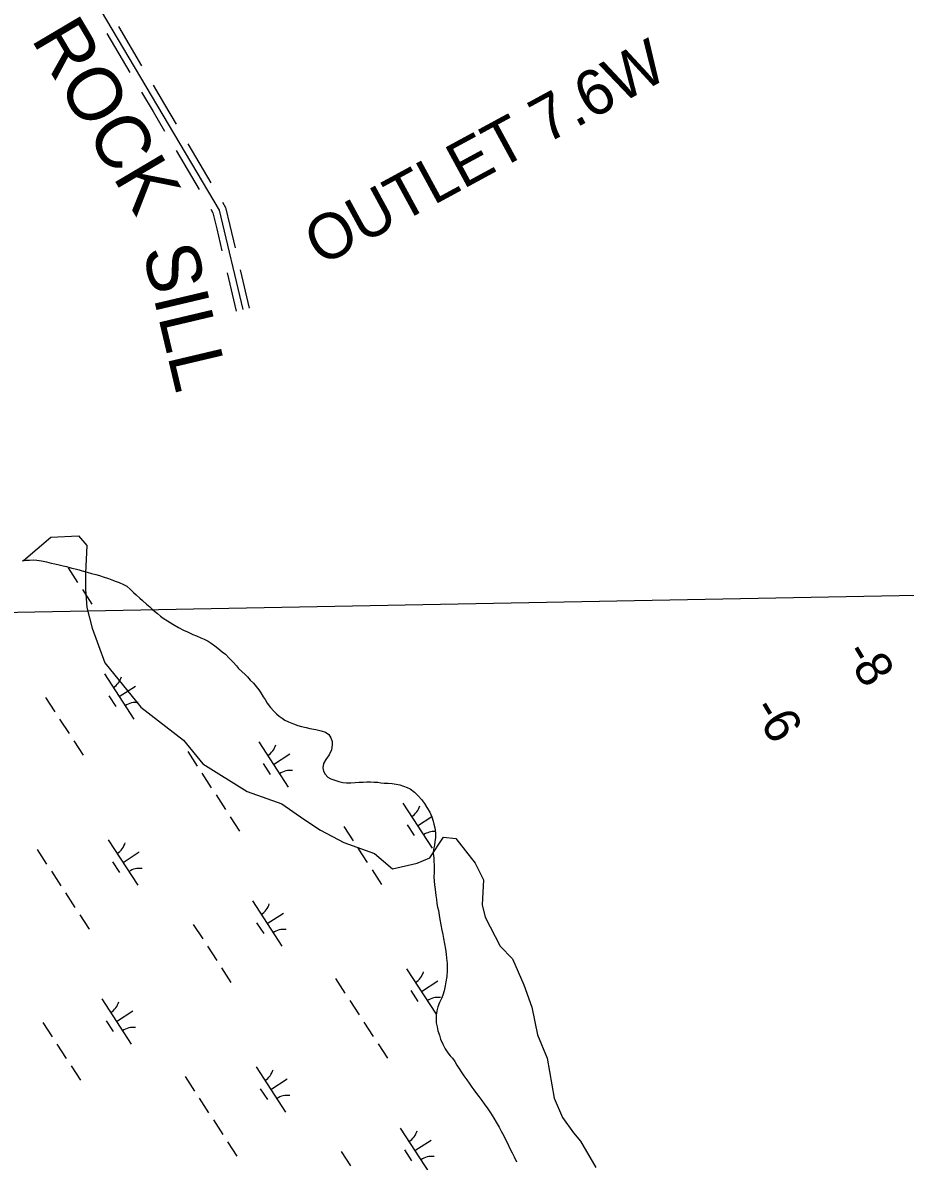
# Model space of a CAD drawing. Extents: x 3953924 to 3974542, y 193747 to 216192.
# Drawn here: x 3961535 to 3962352, y 205842 to 206897 of the extents above; entities that cross this region are included whole.
import ezdxf

# ---------------------------------------------------------------- set-up
doc = ezdxf.new("R2010")
doc.units = 0
for name, color, linetype in [('V-GRID-MAJR', 7, 'Continuous'), ('V-RIVR-EDGE', 7, 'Continuous'), ('V-RIVR-RANG', 7, 'Continuous'), ('V-RRAP-DIKE', 7, 'Continuous'), ('V-RRAP-SILL-IDEN', 7, 'Continuous'), ('V-WETL-SWMP', 7, 'Continuous')]:
    doc.layers.add(name, color=color, linetype=linetype)

msp = doc.modelspace()

# ---------------------------------------------------------------- linework, layer by layer
at = {"layer": 'V-GRID-MAJR'}
msp.add_spline([(3959356.8, 206310.4), (3962493.7, 206368.6), (3967818.6, 206468.2), (3970066, 206510.4)], degree=3, dxfattribs=at)
at = {"layer": 'V-RIVR-EDGE'}
msp.add_lwpolyline([(3961535.6, 206398.3), (3961560.9, 206420.1), (3961586.5, 206421.4), (3961594.2, 206412.4), (3961592.9, 206386.8), (3961592.9, 206371.5), (3961594.2, 206354.8), (3961599.3, 206335.6), (3961610.8, 206303.6), (3961644.1, 206262.6), (3961683.8, 206231.9), (3961701.8, 206210.1), (3961742.7, 206184.5), (3961774.7, 206173), (3961795.2, 206158.9), (3961810.6, 206148.6), (3961832.4, 206137.1), (3961860.6, 206126.9), (3961877.2, 206112.8), (3961900.3, 206117.9), (3961911.8, 206123), (3961924.6, 206142.2), (3961936.1, 206140.9), (3961954, 206117.9), (3961961.7, 206102.5), (3961960.4, 206079.5), (3961963, 206068), (3961977.1, 206041.1), (3961988.6, 206029.5), (3961998.9, 206005.2), (3962006.5, 205984.7), (3962011.7, 205959.1), (3962020.6, 205937.3), (3962027, 205900.2), (3962034.7, 205882.3), (3962045, 205868.2), (3962051.4, 205860.5), (3962065.5, 205836.2)], dxfattribs=at)
at = {"layer": 'V-RRAP-DIKE'}
for points in [[(3961596.7, 206925.9), (3961716.9, 206722.9), (3961738.7, 206630.9)], [(3961612.7, 206886.6), (3961634.1, 206850.4)], [(3961623.5, 206893), (3961644.9, 206856.8)], [(3961644.8, 206832.4), (3961655.5, 206814.3)], [(3961655.6, 206838.7), (3961666.3, 206820.7)], [(3961655.5, 206814.3), (3961666.2, 206796.2)], [(3961666.3, 206820.7), (3961677, 206802.6)], [(3961687.7, 206784.5), (3961709.1, 206748.4)], [(3961676.9, 206778.2), (3961698.3, 206742)], [(3961719.8, 206730.3), (3961722.7, 206725.3), (3961726.7, 206708.7)], [(3961709, 206723.9), (3961711, 206720.6), (3961714.5, 206705.8)], [(3961714.5, 206705.8), (3961719.3, 206685.4)], [(3961726.7, 206708.7), (3961731.5, 206688.2)], [(3961724.2, 206664.9), (3961732.6, 206629.4)], [(3961736.3, 206667.8), (3961744.7, 206632.3)]]:
    msp.add_lwpolyline(points, dxfattribs=at)
at = {"layer": 'V-WETL-SWMP'}
for p, q in [((3961534.2, 206398.1), (3961537.9, 206398.6)), ((3961537.9, 206398.6), (3961541.2, 206398.8)), ((3961541.2, 206398.8), (3961544.4, 206399.1)), ((3961544.4, 206399.1), (3961547.9, 206398.8)), ((3961547.9, 206398.8), (3961552.2, 206398.1)), ((3961552.2, 206398.1), (3961556.8, 206397.2)), ((3961556.8, 206397.2), (3961561.2, 206396)), ((3961561.2, 206396), (3961564.6, 206395.2)), ((3961564.6, 206395.2), (3961568.6, 206394.5)), ((3961568.6, 206394.5), (3961572.3, 206393.5)), ((3961572.3, 206393.5), (3961575.3, 206392.8)), ((3961575.3, 206392.8), (3961580.4, 206391.3)), ((3961577, 206391.5), (3961585.7, 206378.1)), ((3961580.4, 206391.3), (3961583.5, 206390.7)), ((3961583.5, 206390.7), (3961587, 206389.8)), ((3961587, 206389.8), (3961590, 206388.7)), ((3961590, 206388.7), (3961594.6, 206387.7)), ((3961594.6, 206387.7), (3961598.5, 206386.5)), ((3961598.5, 206386.5), (3961602.5, 206385.5)), ((3961602.5, 206385.5), (3961605.9, 206384.6)), ((3961605.9, 206384.6), (3961609.3, 206383.3)), ((3961609.3, 206383.3), (3961614.2, 206381.7)), ((3961614.2, 206381.7), (3961617.5, 206380.5)), ((3961617.5, 206380.5), (3961621.3, 206379.1)), ((3961621.3, 206379.1), (3961624.2, 206378.1)), ((3961590.1, 206371.4), (3961598.8, 206357.9)), ((3961624.2, 206378.1), (3961628.3, 206376.3)), ((3961628.3, 206376.3), (3961631.4, 206374.5)), ((3961631.4, 206374.5), (3961634.7, 206371.5)), ((3961634.7, 206371.5), (3961637.5, 206368.8)), ((3961637.5, 206368.8), (3961639.8, 206366.7)), ((3961639.8, 206366.7), (3961643.3, 206363.5)), ((3961643.3, 206363.5), (3961645.8, 206361.5)), ((3961645.8, 206361.5), (3961649.6, 206358)), ((3961649.6, 206358), (3961652.5, 206355.4)), ((3961652.5, 206355.4), (3961655.4, 206352.8)), ((3961655.4, 206352.8), (3961659.6, 206349.4)), ((3961659.6, 206349.4), (3961662.3, 206346.9)), ((3961662.3, 206346.9), (3961665, 206345)), ((3961665, 206345), (3961668.8, 206342.4)), ((3961668.8, 206342.4), (3961673.9, 206339.3)), ((3961673.9, 206339.3), (3961679.1, 206336.4)), ((3961679.1, 206336.4), (3961683.7, 206334)), ((3961683.7, 206334), (3961687.4, 206332.4)), ((3961687.4, 206332.4), (3961692.5, 206330)), ((3961692.5, 206330), (3961695.7, 206328.7)), ((3961695.7, 206328.7), (3961699.9, 206326.9)), ((3961699.9, 206326.9), (3961702.9, 206325.4)), ((3961702.9, 206325.4), (3961706.6, 206323.6)), ((3961706.6, 206323.6), (3961709.5, 206321.9)), ((3961709.5, 206321.9), (3961712.8, 206319.4)), ((3961712.8, 206319.4), (3961715.7, 206317.3)), ((3961715.7, 206317.3), (3961719.7, 206313.9)), ((3961719.7, 206313.9), (3961722.6, 206311.5)), ((3961722.6, 206311.5), (3961726, 206307.9)), ((3961726, 206307.9), (3961729.7, 206304.3)), ((3961729.7, 206304.3), (3961732.7, 206300.9)), ((3961732.7, 206300.9), (3961734.8, 206298.5)), ((3961734.8, 206298.5), (3961737.7, 206295.5)), ((3961737.7, 206295.5), (3961740.8, 206292.7)), ((3961610.6, 206293.3), (3961637.9, 206251.4)), ((3961740.8, 206292.7), (3961743, 206290.5)), ((3961743, 206290.5), (3961745.6, 206287.7)), ((3961745.6, 206287.7), (3961748.6, 206284.7)), ((3961748.6, 206284.7), (3961751.2, 206281.7)), ((3961614.5, 206273.1), (3961621.1, 206263.1)), ((3961624.3, 206272.3), (3961639.4, 206282.1)), ((3961751.2, 206281.7), (3961753.5, 206278.6)), ((3961753.5, 206278.6), (3961755.3, 206275.8)), ((3961755.3, 206275.8), (3961757.6, 206272)), ((3961555.9, 206271.6), (3961564.6, 206258.2)), ((3961757.6, 206272), (3961759.4, 206269.5)), ((3961759.4, 206269.5), (3961761.3, 206266.3)), ((3961761.3, 206266.3), (3961764.3, 206262.2)), ((3961764.3, 206262.2), (3961767.4, 206258.8)), ((3961767.4, 206258.8), (3961769.9, 206256.4)), ((3961769.9, 206256.4), (3961772.3, 206254.3)), ((3961772.3, 206254.3), (3961775.1, 206252.4)), ((3961775.1, 206252.4), (3961777.7, 206250.6)), ((3961569, 206251.5), (3961577.7, 206238.1)), ((3961777.7, 206250.6), (3961781, 206248.9)), ((3961781, 206248.9), (3961785.6, 206247.2)), ((3961785.6, 206247.2), (3961789.7, 206245.7)), ((3961789.7, 206245.7), (3961793.1, 206244.7)), ((3961793.1, 206244.7), (3961797.5, 206243.6)), ((3961797.5, 206243.6), (3961800.9, 206242.8)), ((3961800.9, 206242.8), (3961806.3, 206241.7)), ((3961806.3, 206241.7), (3961811.4, 206240.7)), ((3961582.1, 206231.4), (3961590.8, 206218)), ((3961811.4, 206240.7), (3961815.3, 206239.5)), ((3961815.3, 206239.5), (3961818.5, 206237.3)), ((3961818.5, 206237.3), (3961820.3, 206234.2)), ((3961820.3, 206234.2), (3961821.3, 206230.8)), ((3961821.3, 206230.8), (3961821.5, 206227.5)), ((3961687.7, 206221.4), (3961696.4, 206208)), ((3961753.5, 206230.3), (3961780.8, 206188.4)), ((3961820.8, 206223), (3961818.7, 206218.4)), ((3961821.5, 206227.5), (3961820.8, 206223)), ((3961757.4, 206210.2), (3961764, 206200.1)), ((3961767.2, 206209.4), (3961782.2, 206219.2)), ((3961813.5, 206210.2), (3961812.9, 206206.4)), ((3961815.7, 206214.2), (3961813.5, 206210.2)), ((3961818.7, 206218.4), (3961815.7, 206214.2)), ((3961700.8, 206201.3), (3961709.5, 206187.9)), ((3961812.9, 206206.4), (3961813.5, 206203.3)), ((3961813.5, 206203.3), (3961814.9, 206200.5)), ((3961814.9, 206200.5), (3961817.4, 206197.8)), ((3961817.4, 206197.8), (3961820.1, 206196)), ((3961820.1, 206196), (3961823.8, 206194.8)), ((3961823.8, 206194.8), (3961827.5, 206193.7)), ((3961827.5, 206193.7), (3961831.3, 206192.8)), ((3961831.3, 206192.8), (3961834.8, 206192.4)), ((3961834.8, 206192.4), (3961838.8, 206192.3)), ((3961838.8, 206192.3), (3961842.6, 206192.7)), ((3961842.6, 206192.7), (3961846.6, 206192.9)), ((3961846.6, 206192.9), (3961850.3, 206193.1)), ((3961850.3, 206193.1), (3961853.6, 206193.4)), ((3961853.6, 206193.4), (3961856.8, 206193.3)), ((3961856.8, 206193.3), (3961860.2, 206193.1)), ((3961860.2, 206193.1), (3961863.6, 206193.1)), ((3961863.6, 206193.1), (3961866.5, 206192.3)), ((3961866.5, 206192.3), (3961869.6, 206192.2)), ((3961869.6, 206192.2), (3961873.3, 206192)), ((3961873.3, 206192), (3961877, 206191.8)), ((3961877, 206191.8), (3961880.7, 206191.1)), ((3961880.7, 206191.1), (3961884, 206190.6)), ((3961884, 206190.6), (3961887.6, 206189.4)), ((3961887.6, 206189.4), (3961891, 206188)), ((3961713.9, 206181.2), (3961722.6, 206167.7)), ((3961891, 206188), (3961893.8, 206186.8)), ((3961893.8, 206186.8), (3961897.8, 206183.9)), ((3961897.8, 206183.9), (3961901.3, 206180.1)), ((3961901.3, 206180.1), (3961904.1, 206176.9)), ((3961886.9, 206173.7), (3961914.2, 206131.8)), ((3961904.1, 206176.9), (3961906.9, 206173.2)), ((3961906.9, 206173.2), (3961909.2, 206169.7)), ((3961909.2, 206169.7), (3961911.8, 206165.2)), ((3961727, 206161), (3961735.7, 206147.6)), ((3961900.6, 206152.7), (3961913.6, 206161.2)), ((3961911.8, 206165.2), (3961913.8, 206160.8)), ((3961913.8, 206160.8), (3961914.9, 206157)), ((3961914.9, 206157), (3961915.7, 206154.1)), ((3961832.2, 206152), (3961840.9, 206138.6)), ((3961890.8, 206153.6), (3961897.4, 206143.5)), ((3961915.7, 206154.1), (3961916.4, 206150.6)), ((3961916.4, 206150.6), (3961917.2, 206146)), ((3961614.1, 206139.6), (3961641.4, 206097.7)), ((3961916.6, 206138), (3961916.1, 206134.8)), ((3961917, 206141.4), (3961916.6, 206138)), ((3961917.2, 206146), (3961917, 206141.4)), ((3961548.3, 206130.6), (3961557, 206117.2)), ((3961627.8, 206118.6), (3961642.8, 206128.4)), ((3961845.3, 206131.9), (3961854, 206118.5)), ((3961915.4, 206131), (3961915.1, 206127)), ((3961915.1, 206127), (3961915.5, 206122.9)), ((3961916.1, 206134.8), (3961915.4, 206131)), ((3961618, 206119.4), (3961624.6, 206109.4)), ((3961915.5, 206122.9), (3961915.7, 206119.5)), ((3961915.7, 206119.5), (3961915.9, 206116.4)), ((3961915.9, 206116.4), (3961915.8, 206113.3)), ((3961561.4, 206110.5), (3961570.1, 206097.1)), ((3961858.4, 206111.8), (3961867.1, 206098.4)), ((3961915.8, 206109.3), (3961915.7, 206105.3)), ((3961915.7, 206105.3), (3961915.8, 206101.3)), ((3961915.8, 206113.3), (3961915.8, 206109.3)), ((3961915.8, 206101.3), (3961916.1, 206098)), ((3961916.1, 206098), (3961916.8, 206093.5)), ((3961916.8, 206093.5), (3961917.4, 206088.2)), ((3961574.5, 206090.4), (3961583.2, 206077)), ((3961747.5, 206083), (3961774.8, 206041)), ((3961917.4, 206088.2), (3961918, 206084.5)), ((3961918, 206084.5), (3961918.5, 206080.8)), ((3961918.5, 206080.8), (3961919.1, 206077.4)), ((3961919.1, 206077.4), (3961919.9, 206074.3)), ((3961919.9, 206074.3), (3961920.6, 206069.7)), ((3961587.6, 206070.3), (3961596.3, 206056.9)), ((3961751.4, 206062.8), (3961758, 206052.8)), ((3961761.2, 206062), (3961776.3, 206071.8)), ((3961920.6, 206069.7), (3961921.2, 206065.7)), ((3961921.2, 206065.7), (3961922.1, 206061)), ((3961692.8, 206061.3), (3961701.5, 206047.9)), ((3961922.1, 206061), (3961923.1, 206056)), ((3961923.1, 206056), (3961924, 206051.8)), ((3961924, 206051.8), (3961924.6, 206048.2)), ((3961705.9, 206041.2), (3961714.6, 206027.7)), ((3961924.6, 206048.2), (3961925.5, 206043.2)), ((3961925.5, 206043.2), (3961926.5, 206038.3)), ((3961926.5, 206038.3), (3961926.9, 206033.6)), ((3961926.9, 206033.6), (3961927.4, 206030)), ((3961719, 206021), (3961727.7, 206007.6)), ((3961890.4, 206020), (3961917.7, 205978.1)), ((3961927.4, 206030), (3961927.8, 206025)), ((3961927.8, 206025), (3961927.9, 206018.6)), ((3961824.6, 206011.1), (3961833.3, 205997.6)), ((3961927.6, 206013.1), (3961926.8, 206008)), ((3961927.9, 206018.6), (3961927.6, 206013.1)), ((3961894.3, 205999.9), (3961900.9, 205989.8)), ((3961904.1, 205999), (3961919.2, 206008.9)), ((3961925.1, 205999.8), (3961923.8, 205995.8)), ((3961926.2, 206004.3), (3961925.1, 205999.8)), ((3961926.8, 206008), (3961926.2, 206004.3)), ((3961608.1, 205992.2), (3961635.4, 205950.3)), ((3961837.7, 205990.9), (3961846.4, 205977.5)), ((3961921, 205989), (3961919.4, 205984.9)), ((3961922.8, 205992.7), (3961921, 205989)), ((3961923.8, 205995.8), (3961922.8, 205992.7)), ((3961621.8, 205971.3), (3961636.9, 205981.1)), ((3961918.4, 205981.2), (3961917.8, 205977.1)), ((3961919.4, 205984.9), (3961918.4, 205981.2)), ((3961553.4, 205970.5), (3961562.1, 205957.1)), ((3961612, 205972.1), (3961618.6, 205962)), ((3961850.8, 205970.8), (3961859.5, 205957.4)), ((3961917.8, 205977.1), (3961917.7, 205973.9)), ((3961917.7, 205973.9), (3961917.8, 205970.1)), ((3961917.8, 205970.1), (3961918.6, 205966.5)), ((3961918.6, 205966.5), (3961919.4, 205962.8)), ((3961919.4, 205962.8), (3961920.7, 205958.6)), ((3961920.7, 205958.6), (3961921.9, 205954.9)), ((3961566.5, 205950.4), (3961575.2, 205937)), ((3961863.9, 205950.7), (3961872.6, 205937.3)), ((3961921.9, 205954.9), (3961923.8, 205950.2)), ((3961923.8, 205950.2), (3961926.1, 205946)), ((3961926.1, 205946), (3961928.7, 205942.3)), ((3961928.7, 205942.3), (3961930.7, 205939.5)), ((3961930.7, 205939.5), (3961932.9, 205937.3)), ((3961932.9, 205937.3), (3961935, 205934.2)), ((3961579.6, 205930.3), (3961588.3, 205916.9)), ((3961751, 205929.2), (3961778.3, 205887.3)), ((3961935, 205934.2), (3961937, 205931)), ((3961937, 205931), (3961938.8, 205928)), ((3961938.8, 205928), (3961941.6, 205923.9)), ((3961685.2, 205920.3), (3961693.9, 205906.9)), ((3961764.7, 205908.3), (3961779.7, 205918.1)), ((3961941.6, 205923.9), (3961943.5, 205921.1)), ((3961943.5, 205921.1), (3961946.1, 205917.4)), ((3961946.1, 205917.4), (3961948.2, 205914.3)), ((3961948.2, 205914.3), (3961950.7, 205910.6)), ((3961754.9, 205909.1), (3961761.5, 205899.1)), ((3961950.7, 205910.6), (3961952.7, 205908)), ((3961952.7, 205908), (3961955.1, 205904.7)), ((3961955.1, 205904.7), (3961957.2, 205901.9)), ((3961698.3, 205900.2), (3961707, 205886.8)), ((3961957.2, 205901.9), (3961960, 205898.1)), ((3961960, 205898.1), (3961962.3, 205895.1)), ((3961962.3, 205895.1), (3961965.6, 205890.3)), ((3961965.6, 205890.3), (3961968, 205886.6)), ((3961968, 205886.6), (3961971.1, 205881.7)), ((3961711.4, 205880.1), (3961720.1, 205866.7)), ((3961884.4, 205872.6), (3961911.7, 205830.7)), ((3961971.1, 205881.7), (3961973.2, 205878)), ((3961973.2, 205878), (3961976, 205873.3)), ((3961976, 205873.3), (3961978, 205869.8)), ((3961898.1, 205851.7), (3961913.2, 205861.5)), ((3961978, 205869.8), (3961980.4, 205865.3)), ((3961980.4, 205865.3), (3961982, 205862.1)), ((3961982, 205862.1), (3961984.1, 205857.9)), ((3961724.5, 205860), (3961733.2, 205846.6)), ((3961829.7, 205851), (3961838.4, 205837.5)), ((3961888.3, 205852.5), (3961894.9, 205842.4)), ((3961984.1, 205857.9), (3961985.8, 205854.4)), ((3961985.8, 205854.4), (3961988.2, 205849.8)), ((3961988.2, 205849.8), (3961989.9, 205846)), ((3961989.9, 205846), (3961992.2, 205841.3))]:
    msp.add_line(p, q, dxfattribs=at)
for centre, start, end in [((3961609.4, 206295.6), 302.2901, 343.8338), ((3961639.5, 206249.3), 82.2901, 123.8337), ((3961752.3, 206232.6), 302.2901, 343.8338), ((3961782.4, 206186.3), 82.2901, 123.8337), ((3961885.7, 206176), 302.2901, 343.8338), ((3961915.9, 206129.7), 86.4118, 123.8337), ((3961612.9, 206141.9), 302.2901, 343.8338), ((3961643, 206095.6), 82.2901, 123.8337), ((3961746.3, 206085.3), 302.2901, 343.8338), ((3961776.4, 206039), 82.2901, 123.8337), ((3961889.2, 206022.3), 302.2901, 343.8338), ((3961606.9, 205994.5), 302.2901, 343.8338), ((3961919.3, 205976), 82.2901, 123.8337), ((3961637, 205948.2), 82.2901, 123.8337), ((3961749.8, 205931.6), 302.2901, 343.8338), ((3961779.9, 205885.3), 82.2901, 123.8337), ((3961883.2, 205875), 302.2901, 343.8338), ((3961913.4, 205828.7), 82.2901, 123.8337)]:
    msp.add_arc(centre, 17.6, start, end, dxfattribs=at)

# ---------------------------------------------------------------- texts
at = {"layer": 'V-RIVR-RANG'}
for s, p in [('-8', (3962294.8, 206312.7)), ('-6', (3962209.5, 206260.7))]:
    msp.add_text(s, height=33.5, rotation=301.2005, dxfattribs=at).set_placement(p)
at = {"layer": 'V-RRAP-SILL-IDEN'}
for s, height, rotation, p in [('ROCK', 50, 300.6207, (3961542.1, 206881.7)), ('OUTLET 7.6W', 42, 28.5215, (3961811, 206670.6)), ('SILL', 50, 283.3187, (3961645.6, 206685.9))]:
    msp.add_text(s, height=height, rotation=rotation, dxfattribs=at).set_placement(p)

doc.saveas('drawing.dxf')
